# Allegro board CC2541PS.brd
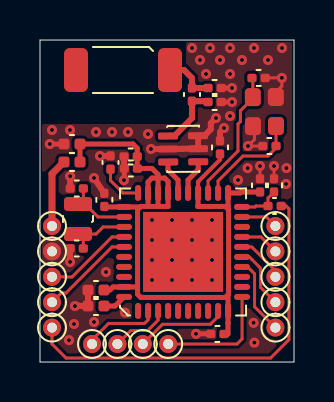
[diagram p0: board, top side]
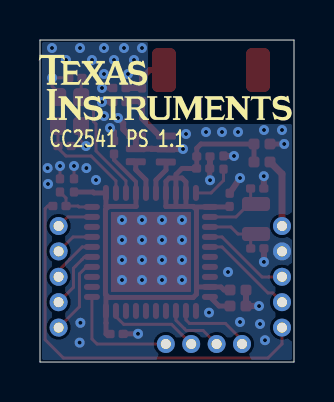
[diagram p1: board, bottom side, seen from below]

Outline 12.7 x 16.1 mm; copper layers: TOP, BOTTOM. Coordinates in mm from the lower left corner of the outline.
Outline path: 0,16.1 0,0 12.7,0 12.7,16.1 0,16.1

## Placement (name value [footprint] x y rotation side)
A1  2450AT42A100  [ANTENNA_2450AT42A100N]  6.5 14.6 180 top
C1  2.2uF  [CAPC1005X60L]  2 10.9 180 top
C101  100nF  [CAPC0603X35N]  9.2 1.4 179.5 top
C201  1000pF  [CAPC0603X35N]  11.7 8.5 90 top
C211  100nF  [CAPC0603X35N]  11 8.5 90 top
C221  12pF  [CAPC0603X35N]  11.8 10.8 180.1 top
C231  12pF  [CAPC0603X35N]  10.6 14.2 0.4 top
C241  100nF  [CAPC0603X35N]  9 10.4 90 top
C251  DNM  [CAPC0603X35N]  8.4 13.7 0 top
C252  DNM  [CAPC0603X35N]  8.4 13 0 top
C271  100nF  [CAPC0603X35N]  4.87 9.68 179.9 top
C272  220pF  [CAPC0603X35N]  4.86 10.28 180.1 top
C311  100nF  [CAPC0603X35N]  3.22 7.78 90.5 top
C321  15pF  [CAPC0603X35N]  2.17 8.68 180 top
C331  15pF  [CAPC0603X35N]  2.16 5.68 179.8 top
C391  1uF  [CAPC1005X60N]  3.2 3.6 180.2 top
C401  1uF  [CAPC1005X60N]  3.2 2.8 180 top
FL1  2450BM15A0002  [FIL_2450BM15A0002N]  6.4 11.3 270.5 top
L1  BLM15HG102SN1  [INDC1005X60L]  1.2 10 0 top
NOREF  -  []  -0.2 15.6 270 bottom
R201  2.7k  [RESC0603X35N]  11.4 7.8 360 top
R251  0  [RESC0603X35N]  7.6 13.7 270 top
R301  56k  [RESC0603X35N]  3.53 10.3 270 top
TP2  TP_0.5MM_PTH  [TP_90X50H]  2.6 0.9 0 top
TP3  TP_0.5MM_PTH  [TP_90X50H]  3.87 0.9 0 top
TP9  TP_0.5MM_PTH  [TP_90X50H]  5.14 0.9 0 top
TP11  TP_0.5MM_PTH  [TP_90X50H]  6.41 0.9 0 top
TP14  TP_0.5MM_PTH  [TP_90X50H]  11.77 1.72 0 top
TP15  TP_0.5MM_PTH  [TP_90X50H]  11.77 2.99 0 top
TP16  TP_0.5MM_PTH  [TP_90X50H]  11.77 4.26 0 top
TP17  TP_0.5MM_PTH  [TP_90X50H]  11.77 5.53 0 top
TP19  TP_0.5MM_PTH  [TP_90X50H]  11.77 6.8 0 top
TP20  TP_0.5MM_PTH  [TP_90X50H]  0.6 1.72 0 top
TP34  TP_0.5MM_PTH  [TP_90X50H]  0.6 4.26 0 top
TP35  TP_0.5MM_PTH  [TP_90X50H]  0.6 2.99 0 top
TPGND  TP_0.5MM_PTH  [TP_90X50H]  0.6 5.53 0 top
TPVDD  TP_0.5MM_PTH  [TP_90X50H]  0.6 6.8 0 top
U1  CC2541F256  [QFNFC50P600X600X100-41AL]  4.9 2.55 0 top
X1  32MHz  [XTAL_FA128L]  11.8 11.8 90.3 top
X2  32.768kHz  [XTAL_FC12MN]  1.9 6.4 90 top

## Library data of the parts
A1 = ANTENNA_2_PIN: User Part Number: #PN; alternate symbols: (ANTENNA_2450AT42A100L,ANTENNA_2450AT42A100M)
C1 C391 C401 = CAPACITOR: alternate symbols: (CAPC1005X60L,CAPC1005X60M)
C101 C201 C211 C221 C231 C241 C271 C272 C311 C321 C331 = CAPACITOR: alternate symbols: (CAPC0603X35L,CAPC0603X35M)
C251 C252 = CAPACITOR: alternate symbols: (CAPC0603X35L,CAPC0603X35N)
FL1 = FILTER_LFB_6PIN: alternate symbols: (FIL_2450BM15A0002L,FIL_2450BM15A0002M)
L1 = INDUCTOR: alternate symbols: (INDC1005X60L,INDC1005X60M)
R201 R251 R301 = RESISTOR: alternate symbols: (RESC0603X35L,RESC0603X35M)
TP2 TP3 TP9 TP11 TP14-TP17 TP19 TP20 TP34 TP35 TPGND TPVDD = TP_LONGPIN
U1 = IC_RF_CC2541_QFN40_V2: alternate symbols: (QFNFC50P600X600X100-41L,QFNFC50P600X600X100-41M,QFNFC50P600X600X100-41AL,QFNFC50P600X600X100-41AM)
X1 = XTAL_4: alternate symbols: (XTAL_FA128L,XTAL_FA128M)
X2 = XTAL: alternate symbols: (XTAL_FC12ML,XTAL_FC12MM)

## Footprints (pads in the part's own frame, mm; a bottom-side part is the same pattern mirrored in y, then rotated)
ANTENNA_2450AT42A100N
  custom 0.3x0.3 smd: 1(0,0) 2(4.7,0)
CAPC0603X35N
  custom 0.105x0.105 smd: 1(0,0) 2(0.66,0)
CAPC1005X60L
  custom 0.135x0.135 smd: 1(0,0) 2(0.8,0)
CAPC1005X60N
  custom 0.135x0.135 smd: 1(0,0) 2(0.8,0)
FIL_2450BM15A0002N
  custom 0.087x0.087 smd: 1(0,0) 2(0.65,0) 3(1.3,0) 4(1.3,1.5) 5(0.65,1.5) 6(0,1.5)
INDC1005X60L
  custom 0.135x0.135 smd: 1(0,0) 2(0.8,0)
QFNFC50P600X600X100-41AL
  oval 0.3x0.8 smd: 1(0,0) 2(0.5,0) 3(1,0) 4(1.5,0) 5(2,0) 6(2.5,0) 7(3,0) 8(3.5,0) 9(4,0) 10(4.5,0) 21(4.5,5.9) 22(4,5.9) 23(3.5,5.9) 24(3,5.9) 25(2.5,5.9) 26(2,5.9) 27(1.5,5.9) 28(1,5.9) 29(0.5,5.9) 30(0,5.9)
  oval 0.8x0.3 smd: 11(5.2,0.7) 12(5.2,1.2) 13(5.2,1.7) 14(5.2,2.2) 15(5.2,2.7) 16(5.2,3.2) 17(5.2,3.7) 18(5.2,4.2) 19(5.2,4.7) 20(5.2,5.2) 31(-0.7,5.2) 32(-0.7,4.7) 33(-0.7,4.2) 34(-0.7,3.7) 35(-0.7,3.2) 36(-0.7,2.7) 37(-0.7,2.2) 38(-0.7,1.7) 39(-0.7,1.2) 40(-0.7,0.7)
  rect 4x4 smd: 41(2.25,2.95)
RESC0603X35N
  custom 0.105x0.105 smd: 1(0,0) 2(0.66,0)
TP_90X50H
  round 0.9 hole 0.5: 1(0,0)
XTAL_FA128L
  custom 0.2x0.2 smd: 1(0,0) 2(1.45,0) 3(1.45,1.15) 4(0,1.15)
XTAL_FC12MN
  custom 0.175x0.175 smd: 1(0,0) 2(1.5,0)

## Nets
GND_SIGNAL: C1.2 C101.2 C201.2 C211.2 C221.2 C231.2 C241.2 C251.2 C252.2 C271.2 C272.2 C311.2 C321.2 C331.2 C391.2 C401.2 FL1.2(GND#2) FL1.5(GND#5) FL1.6(GND#6) R301.1 TPGND.1 U1.41(GND/EGP) X1.2 X1.4
VDD: C1.1 C101.1 C211.1 C241.1 C271.1 C272.1 C311.1 C391.1 L1.2 U1.10(DVDD2) U1.21(AVDD5) U1.24(AVDD3) U1.27(AVDD2) U1.28(AVDD1) U1.29(AVDD4) U1.31(AVDD6) U1.39(DVDD1)
P0_0: TP19.1 U1.19(P0_0)
P0_2: TP17.1 U1.17(P0_2)
P0_3: TP16.1 U1.16(P0_3)
P0_4: TP15.1 U1.15(P0_4)
P0_5: TP14.1 U1.14(P0_5)
P1_0: TP11.1 U1.11(P1_0)
P1_1: TP9.1 U1.9(P1_1)
P2_1: TP35.1 U1.35(P2_1)
P2_2: TP34.1 U1.34(P2_2)
RESET_N: C201.1 R201.1 U1.20(NRESET)
SCL: TP2.1 U1.2(SCL)
SDA: TP3.1 U1.3(SDA)
N173251: L1.1 TPVDD.1
N231514: C331.1 U1.33(P2_3/XOSC32K_Q2) X2.1
N231518: C321.1 U1.32(P2_4/XOSC32K_Q1) X2.2
N239349: FL1.4(BP2) U1.25(RF_P)
N239359: FL1.3(BP1) U1.26(RF_N)
N239704: C401.1 U1.40(DCOUPL)
N239709: R301.2 U1.30(RBIAS)
N249929: A1.1(FEEDING) C251.1 R251.1
N252810: C231.1 U1.23(XOSC_Q2) X1.3
N252820: C221.1 U1.22(XOSC_Q1) X1.1
N256510: C252.1 FL1.1(UBP) R251.2
N2562571: R201.2 TP20.1

Pads without a net: A1 2; U1 1 4 5 6 7 8 12 13 18 36 37 38

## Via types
v1: diameter 0.5, hole 0.2, TOP to BOTTOM, 62 vias

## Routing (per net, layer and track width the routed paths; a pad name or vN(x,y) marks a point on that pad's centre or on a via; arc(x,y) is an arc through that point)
GND_SIGNAL: length 18.2
  TOP w0.15: C211.2 v1(11,9.8) ; C231.2 11.69,14.21 12.09,14.21 v1(12.09,14.2) 12.09,13.8 11.77,13.48 11.77,13.27 X1.2 ; 10.65,11.79 10.72,11.72 10.72,11.12 v1(10.4,10.8) C221.2 ; 4.21,9.11 4.2,9.1 v1(4.2,9.09) ; C201.2 v1(11.7,9.8)
  TOP w0.25: C1.2 v1(0.49,10.9) ; C271.2 4.21,9.11 ; v1(7.8,1.41) 8,1.41 8.54,1.4 ; C252.2 v1(9.6,13) ; C251.2 v1(9.6,13.7)
  TOP w0.3: v1(2.7,9.2) 3.21,8.44 ; 2.4,3.6 C401.2 1.97,2.8 1.96,2.81 1.96,2.81 1.85,2.81 1.86,2.8 1.86,2.8 v1(1.75,2.8) ; R301.1 3.4,10.3 3.4,10.3 v1(3,10.3) ; C331.2 1.5,5.27 v1(1.5,5) ; v1(8.8,12.2) 8.54,11.94 8.54,11.64 8.23,11.32 7.9,11.31 7.91,11.31 FL1.5 7.12,10.66 7.11,10.66 FL1.2 5.7,10.64 5.7,10.65 v1(5.55,10.65) ; 1.51,8.68 v1(1.51,9.29) ; C241.2 9,11.5 v1(9.2,11.7) ; C271.2 4.2,9.69 C272.2
  vias: v1(0.6,11.6) v1(1.5,11.6) v1(1.45,1.09) v1(1.7,1.9) v1(2.7,2) v1(2.8,11.5) v1(3.3,4.5) v1(3.6,11.5) v1(4.25,2.47) v1(4.4,11.5) v1(5.4,11.4) v1(5.6,7.1) v1(5.6,6.1) v1(5.6,5.1) v1(5.6,4.1) v1(6.6,7.1) v1(6.6,6.1) v1(6.6,5.1) v1(6.6,4.1) v1(7.6,15.7) v1(7.6,7.1) v1(7.6,6.1) v1(7.6,5.1) v1(7.6,4.1) v1(8,15.1) v1(8.3,14.4) v1(8.5,15.7) v1(8.6,7.1) v1(8.6,6.1) v1(8.6,5.1) v1(8.6,4.1) v1(9,15.1) v1(9.5,15.7) v1(9.5,14.4) v1(9.5,12.3) v1(9.9,9.1) v1(10.1,15.1) v1(10.38,9.7) v1(10.7,15.7) v1(10.68,1.96) v1(10.72,0.97) v1(11.4,15.1) v1(12.1,15.7) v1(12.32,9.7) v1(12.3,8.9)
VDD: length 38.8
  TOP w0.2: U1.24 7.9,9.01 9,10.11 C241.1
  TOP w0.25: 9.4,3.36 U1.10 9.4,1.95 9.4,1.95 9.4,1.4 C101.1 ; 9.4,3.36 9.27,3.23 5.04,3.23 4.88,3.39 4.88,3.7 ; 9.4,3.36 9.43,3.39 9.43,7.62 9.4,7.64 9.4,7.8 ; 4.88,3.7 4.83,3.75 U1.39 3.65,3.75 3.5,3.6 C391.1 ; 4.88,3.7 4.88,7.62 5.01,7.75 ; 5.4,7.8 5.38,7.78 5.04,7.78 5.01,7.75 ; 5.4,7.8 5.43,7.78 5.88,7.78 5.9,7.8 ; 5.4,7.8 U1.29 5.4,9 5.6,9.2 5.9,9.2 ; 5.9,9.2 U1.28 5.9,7.8 ; 5.9,9.2 6.24,9.2 6.4,9.03 U1.27 6.4,7.78 6.4,7.78 5.93,7.78 5.9,7.8 ; 5.9,9.2 5.9,9.2 ; 5.9,9.2 5.9,9.38 5.6,9.68 5.31,9.68 5.31,9.68 C271.1 4.86,9.69 C272.1 4.86,10.69 4.65,10.9 C1.1 L1.2 ; 9.4,7.8 9.32,7.72 9.27,7.78 7.93,7.78 7.9,7.8 ; 9.4,7.8 U1.21 10,8.45 10.05,8.5 C211.1 ; 7.9,7.8 U1.24 ; 7.9,7.8 7.88,7.78 ; 5.01,7.75 U1.31 3.25,7.75 C311.1
P0_0: length 1.9
  TOP w0.15: U1.19 11.32,7.25 TP19.1
P0_2: length 2
  TOP w0.15: TP17.1 11.05,6.25 U1.17
P0_3: length 2.5
  TOP w0.15: TP16.1 11.77,4.57 11.22,5.12 10.59,5.75 U1.16
P0_4: length 3.2
  TOP w0.15: TP15.1 11.03,3.73 11.03,4.69 10.93,4.78 10.59,5.13 10.59,5.13 10.47,5.25 U1.15
P0_5: length 3.9
  TOP w0.15: U1.14 10.38,4.75 10.73,4.41 10.73,2.76 TP14.1
P1_0: length 5.9
  TOP w0.15: TP11.1 9.85,0.9 10.1,1.15 U1.11
P1_1: length 4.6
  TOP w0.15: TP9.1 5.6,1.36 5.6,1.36 6.12,1.88 8.52,1.88 8.9,2.27 U1.9
P2_1: length 4.7
  TOP w0.15: TP35.1 1.06,3.45 1.3,3.45 3.6,5.75 U1.35
P2_2: length 4.4
  TOP w0.15: TP34.1 1.25,4.26 1.26,4.25 1.6,4.25 3.6,6.25 U1.34
RESET_N: length 2.1
  TOP w0.15: U1.20 10.75,7.75 10.8,7.8 R201.1 11.4,8.2 C201.1
SCL: length 3.9
  TOP w0.15: U1.2 5.4,2.1 5.23,1.93 3.43,1.93 2.6,1.1 TP2.1
SDA: length 3
  TOP w0.15: TP3.1 4.55,1.57 5.39,1.57 5.48,1.66 5.48,1.66 5.9,2.09 U1.3
N173251: length 3.5
  TOP w0.35: L1.1 1.2,10 0.6,9.41 TPVDD.1
N231514: length 3.3
  TOP w0.15: U1.33 3.16,6.75 2.8,6.4 X2.1 2.16,6.14 C331.1
N231518: length 3.5
  TOP w0.15: C321.1 2.17,8.17 X2.2 2.25,7.9 2.9,7.25 U1.32
N239349: length 1.8
  TOP w0.25: 7.91,10.01 7.91,9.64 7.9,9.62 7.9,9.6 7.4,9.1 U1.25
N239359: length 1.8
  TOP w0.25: U1.26 6.9,9.1 6.4,9.6 6.4,9.99 FL1.3
N239704: length 1.2
  TOP w0.25: C401.1 3.75,2.8 U1.40
N239709: length 2.2
  TOP w0.15: 3.53,9.64 3.53,9.08 4.15,8.45 U1.30
N249929: length 2.6
  TOP w0.3: C251.1 R251.1 7.6,14.2 7.2,14.6 A1.1
N252810: length 6.7
  TOP w0.15: C231.1 10.64,14.16 X1.3 10.64,13.19 10.02,12.56 10.02,12.33 10.02,12.02 9.9,11.9 9.9,10.55 8.4,9.05 U1.23
N252820: length 5.3
  TOP w0.15: X1.1 C221.1 11.8,10.7 11.4,10.3 10.15,10.3 8.9,9.05 U1.22
N256510: length 3.2
  TOP w0.3: FL1.1 6.73,11.3 7.6,12.19 R251.2 8.36,13.04 C252.1
N2562571: length 20.4
  TOP w0.15: TP20.1 0.6,0.9 1.3,0.2 11.53,0.2 12.45,1.11 12.45,7.66 12.31,7.8 R201.2 12,7.74

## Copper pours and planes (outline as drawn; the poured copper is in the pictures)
GND_SIGNAL on TOP: 0.1,0.1 0.1,11.9 7.3,11.9 7.3,16 12.6,16 12.6,0.1 ; 3 cut-outs
GND_SIGNAL on BOTTOM: 0.1,0.1 0.1,11.9 7.3,11.9 7.3,16 12.6,16 12.6,0.1

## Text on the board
Ref Des/Silkscreen Bottom: CC2541 PS 1.1
XSECTION_CHART: L1: TOP CONDUCTOR - COPPER 0.035 MM | *  DIELECTRIC - FR-4 0.8 MM | L2: BOTTOM CONDUCTOR - COPPER 0.035 MM | DESIGN CROSS SECTION CHART | ___________________________ | TOTAL THICKNESS 0.87 MM
User.5: FIGURE | SIZE | 0.2 | 0.5 | DRILL CHART: TOP to BOTTOM | ALL UNITS ARE IN MILLIMETERS | PLATED | QTY | 62 | 14
